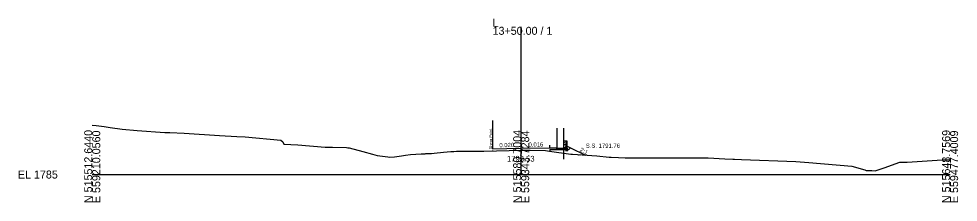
# Model space of a CAD drawing. Extents: x -26 to 1303, y -10 to 9545.
# Drawn here: x 974.3 to 1302.8, y -9.7 to 54.5 of the extents above; entities that cross this region are included whole.
import ezdxf

# ---------------------------------------------------------------- set-up
doc = ezdxf.new("R2010")
doc.units = 0
for name, color, linetype in [('Exist Cross Section Cell', 7, 'Continuous'), ('Exist XS Center Line Elevation Label', 7, 'Continuous'), ('Exist XS Ground Line', 7, 'Continuous'), ('Prop XS Ditch Slope Text', 7, 'Continuous'), ('Prop XS Dump Level', 7, 'Continuous'), ('Prop XS EOT Tick Mark', 7, 'Continuous'), ('Prop XS Finish Grade', 7, 'Continuous'), ('Prop XS Finish Grade Earthwork', 7, 'Continuous'), ('Prop XS Finish Grade Paved Shoulder', 7, 'Continuous'), ('Prop XS Finish Grade Pavement', 7, 'Continuous'), ('Prop XS Guardrail', 7, 'Continuous'), ('Prop XS Pvmt Edge Slope', 7, 'Continuous'), ('Prop XS SE Text', 7, 'Continuous'), ('Prop XS Shear Point Label', 7, 'Continuous'), ('Prop XS SS Elevation Text', 7, 'Continuous'), ('Prop XS Subgrade Earthwork', 7, 'Continuous'), ('Scratch_Level_3', 7, 'Continuous'), ('Typical Curb CELL', 7, 'Continuous')]:
    doc.layers.add(name, color=color, linetype=linetype)

msp = doc.modelspace()

# ---------------------------------------------------------------- linework, layer by layer
at = {"layer": 'Exist Cross Section Cell'}
for p, q in [((1150, 0), (1150, 51.7)), ((1000, 0), (1150, 0)), ((1150, 0), (1300, 0))]:
    msp.add_line(p, q, dxfattribs=at)
at = {"layer": 'Exist XS Ground Line'}
for p, q in [((1000, 17.23), (1001.31, 17.11)), ((1001.31, 17.11), (1004.18, 16.78)), ((1004.18, 16.78), (1006.31, 16.45)), ((1006.31, 16.45), (1010.43, 15.93)), ((1010.43, 15.93), (1015.71, 15.39)), ((1015.71, 15.39), (1025.36, 14.72)), ((1025.36, 14.72), (1027.12, 14.69)), ((1027.12, 14.69), (1032.14, 14.52)), ((1032.14, 14.52), (1044.48, 13.7)), ((1044.48, 13.7), (1050.57, 13.35)), ((1050.57, 13.35), (1053.5, 13.14)), ((1053.5, 13.14), (1065.92, 12.02)), ((1065.92, 12.02), (1066.7, 11.39)), ((1066.7, 11.39), (1067, 10.67)), ((1067, 10.67), (1071.91, 10.36)), ((1071.91, 10.36), (1081.49, 9.6)), ((1081.49, 9.6), (1084, 9.63)), ((1084, 9.63), (1088.9, 9.44)), ((1088.9, 9.44), (1089.4, 9.37)), ((1089.4, 9.37), (1089.83, 9.37)), ((1089.83, 9.37), (1094.6, 8.04)), ((1094.6, 8.04), (1098.01, 7.11)), ((1098.01, 7.11), (1099.63, 6.65)), ((1099.63, 6.65), (1103.33, 6.16)), ((1108.15, 6.56), (1109.53, 6.78)), ((1109.53, 6.78), (1111.33, 7.06)), ((1111.33, 7.06), (1115, 7.2)), ((1115, 7.2), (1116.38, 7.29)), ((1116.38, 7.29), (1116.69, 7.31)), ((1116.69, 7.31), (1118.67, 7.4)), ((1118.67, 7.4), (1119.53, 7.47)), ((1119.53, 7.47), (1122.8, 7.78)), ((1122.8, 7.78), (1125.41, 8)), ((1125.41, 8), (1126.5, 8.11)), ((1126.5, 8.11), (1127.42, 8.22)), ((1127.42, 8.22), (1131.99, 8.19)), ((1131.99, 8.19), (1134.79, 8.15)), ((1134.79, 8.15), (1136.91, 8.12)), ((1136.91, 8.12), (1150.25, 8.54)), ((1150.25, 8.54), (1153.09, 8.5)), ((1153.09, 8.5), (1158.52, 8.38)), ((1158.52, 8.38), (1159.93, 8.13)), ((1159.93, 8.13), (1167.33, 7.13)), ((1167.33, 7.13), (1167.94, 7.08)), ((1167.94, 7.08), (1176.46, 6.49)), ((1103.33, 6.16), (1103.78, 6.09)), ((1103.78, 6.09), (1105.66, 6.2)), ((1105.66, 6.2), (1108.15, 6.56)), ((1176.46, 6.49), (1180.77, 6.13)), ((1180.77, 6.13), (1181.47, 6.09)), ((1181.47, 6.09), (1184.09, 5.91)), ((1184.09, 5.91), (1186.4, 5.83)), ((1186.4, 5.83), (1190.13, 5.83)), ((1190.13, 5.83), (1197.44, 5.79)), ((1197.44, 5.79), (1201.62, 5.82)), ((1201.62, 5.82), (1215.35, 5.82)), ((1215.35, 5.82), (1221.27, 5.49)), ((1221.27, 5.49), (1224, 5.41)), ((1224, 5.41), (1224.6, 5.41)), ((1224.6, 5.41), (1227.05, 5.3)), ((1227.05, 5.3), (1246.08, 4.58)), ((1246.08, 4.58), (1250.58, 4.21)), ((1250.58, 4.21), (1265.66, 2.95)), ((1277, 2.32), (1282.43, 4.34)), ((1282.43, 4.34), (1284.95, 4.34)), ((1284.95, 4.34), (1297.27, 5.15)), ((1297.27, 5.15), (1300, 5.1)), ((1265.66, 2.95), (1270.22, 1.59)), ((1270.22, 1.59), (1270.67, 1.43)), ((1270.67, 1.43), (1272.65, 1.36)), ((1272.65, 1.36), (1273.76, 1.29)), ((1273.76, 1.29), (1277, 2.32))]:
    msp.add_line(p, q, dxfattribs=at)
at = {"layer": 'Prop XS Dump Level'}
for p, q in [((1140, 8.97), (1150, 9.17)), ((1150, 9.17), (1160, 9.33))]:
    msp.add_line(p, q, dxfattribs=at)
at = {"layer": 'Prop XS EOT Tick Mark'}
for p, q in [((1140, 8.97), (1140, 9.97)), ((1160, 9.33), (1160, 10.33))]:
    msp.add_line(p, q, dxfattribs=at)
at = {"layer": 'Prop XS Finish Grade'}
for q in [(1165.46, 9.55), (1167.3, 9.36)]:
    msp.add_line((1166.09, 9.96), q, dxfattribs=at)
at = {"layer": 'Prop XS Finish Grade Earthwork'}
msp.add_line((1167.3, 9.36), (1172.49, 6.76), dxfattribs=at)
at = {"layer": 'Prop XS Finish Grade Paved Shoulder'}
msp.add_line((1160, 9.33), (1162.44, 9.29), dxfattribs=at)
at = {"layer": 'Prop XS Finish Grade Pavement'}
for p, q in [((1140, 8.97), (1150, 9.17)), ((1150, 9.17), (1160, 9.33))]:
    msp.add_line(p, q, dxfattribs=at)
at = {"layer": 'Prop XS Guardrail'}
for p, q in [((1164.8, 11.49), (1164.77, 11.43)), ((1164.77, 11.43), (1164.8, 11.37)), ((1164.8, 10.88), (1164.77, 10.82)), ((1164.77, 10.82), (1164.8, 10.76)), ((1165.09, 11.69), (1164.8, 11.49)), ((1164.8, 11.37), (1165.09, 11.17)), ((1165.09, 11.08), (1164.8, 10.88)), ((1164.8, 10.76), (1165.09, 10.56)), ((1165.59, 11.69), (1165.09, 11.69)), ((1165.09, 11.17), (1165.09, 11.08)), ((1165.09, 10.56), (1165.59, 10.56)), ((1166.09, 11.69), (1165.59, 11.69)), ((1165.59, 11.69), (1165.59, 9.19)), ((1166.09, 9.19), (1166.09, 11.69)), ((1165.59, 9.19), (1165.59, 8.23)), ((1166.09, 9.19), (1166.09, 8.23))]:
    msp.add_line(p, q, dxfattribs=at)
at = {"layer": 'Prop XS Pvmt Edge Slope'}
for p, q in [((1165.46, 8.87), (1166.33, 8.87)), ((1166.33, 8.87), (1166.64, 8.7))]:
    msp.add_line(p, q, dxfattribs=at)
at = {"layer": 'Prop XS Shear Point Label'}
msp.add_line((1140, 18.9), (1140, 8.97), dxfattribs=at)
at = {"layer": 'Prop XS Subgrade Earthwork'}
for p, q in [((1140, 8.43), (1140, 8.22)), ((1160, 8.79), (1160.53, 8.8)), ((1160, 8.79), (1160, 8.12)), ((1160.53, 8.8), (1166.64, 8.7)), ((1166.64, 8.7), (1167.3, 9.36))]:
    msp.add_line(p, q, dxfattribs=at)
at = {"layer": 'Scratch_Level_3'}
for p, q in [((1162.44, 16.17), (1162.44, 9.29)), ((1164.77, 16.17), (1164.77, 5.35))]:
    msp.add_line(p, q, dxfattribs=at)
at = {"layer": 'Typical Curb CELL'}
for p, q in [((1162.44, 9.29), (1162.44, 9.29)), ((1162.44, 8.87), (1162.44, 9.28)), ((1165.46, 8.87), (1162.44, 8.87)), ((1162.45, 9.29), (1164.77, 9.21)), ((1162.68, 9.03), (1162.77, 9.15)), ((1162.8, 9.03), (1162.68, 9.03)), ((1162.77, 9.15), (1162.8, 9.03)), ((1163.44, 8.98), (1163.51, 9.09)), ((1163.61, 9.02), (1163.44, 8.98)), ((1163.51, 9.09), (1163.61, 9.02)), ((1163.93, 9.03), (1164.01, 9.15)), ((1164.05, 9.03), (1163.93, 9.03)), ((1164.01, 9.15), (1164.05, 9.03)), ((1164.69, 8.98), (1164.76, 9.09)), ((1164.86, 9.02), (1164.69, 8.98)), ((1164.76, 9.09), (1164.86, 9.02)), ((1164.77, 9.21), (1165.46, 9.55)), ((1165.27, 9.22), (1165.29, 9.13)), ((1165.43, 9.17), (1165.27, 9.22)), ((1165.29, 9.13), (1165.43, 9.17)), ((1165.46, 8.87), (1165.46, 9.55))]:
    msp.add_line(p, q, dxfattribs=at)
for centre in [(1162.53, 9.11), (1162.57, 9.24), (1162.94, 9.16), (1163, 8.99), (1163.05, 8.95), (1163.09, 9.08), (1163.16, 9.08), (1163.21, 9.11), (1163.26, 8.99), (1163.45, 9.03), (1163.66, 9.01), (1163.67, 9.06), (1163.68, 9.12), (1163.74, 8.98), (1163.84, 9.03), (1163.93, 9.04), (1164.05, 8.99), (1164.25, 8.99), (1164.3, 8.95), (1164.33, 9.08), (1164.46, 9.11), (1164.51, 8.99), (1164.7, 9.03), (1164.73, 8.93), (1164.91, 9.01), (1164.92, 9.06), (1165.18, 9.04), (1165.3, 8.99), (1165.4, 9.26)]:
    msp.add_circle(centre, 0.00802, dxfattribs=at)
msp.add_arc((1162.45, 9.28), 0.0104, 87.952, 180, dxfattribs=at)

# ---------------------------------------------------------------- texts
at = {"layer": 'Exist Cross Section Cell'}
for s, p in [('L', (1140, 51.7)), ('13+50.00 / 1', (1140, 48.9)), ('EL 1785', (974, -1.4))]:
    msp.add_text(s, height=2.8, dxfattribs=at).set_placement(p)
for s, p in [('N 515512.6440', (1000, -10)), ('E 559210.0560', (1002.8, -10)), ('N 515580.7004', (1150, -10)), ('E 559343.7284', (1152.8, -10)), ('N 515648.7569', (1300, -10)), ('E 559477.4009', (1302.8, -10))]:
    msp.add_text(s, height=2.8, rotation=90, dxfattribs=at).set_placement(p)
at = {"layer": 'Exist XS Center Line Elevation Label'}
msp.add_text('1793.53', height=2, dxfattribs=at).set_placement((1145.02, 4.53))
at = {"layer": 'Prop XS Ditch Slope Text'}
msp.add_text('2:1', height=1.5, rotation=333.4349, dxfattribs=at).set_placement((1170.35, 8.19))
at = {"layer": 'Prop XS Dump Level'}
for s, height, p in [('Case1', 0.04, (1163, 9.16)), ('Eop', 0.3, (1170, 6.64))]:
    msp.add_text(s, height=height, dxfattribs=at).set_placement(p)
at = {"layer": 'Prop XS SE Text'}
for s, rotation, p in [('0.020', 1.1458, (1142.38, 9.52)), ('0.016', 0.909, (1152.57, 9.71))]:
    msp.add_text(s, height=1.5, rotation=rotation, dxfattribs=at).set_placement(p)
at = {"layer": 'Prop XS Shear Point Label'}
msp.add_text('Shear Point', height=1, rotation=90, dxfattribs=at).set_placement((1139.83, 8.82))
at = {"layer": 'Prop XS SS Elevation Text'}
msp.add_text('S.S. 1791.76', height=1.5, dxfattribs=at).set_placement((1172.59, 9.32))

doc.saveas('drawing.dxf')
